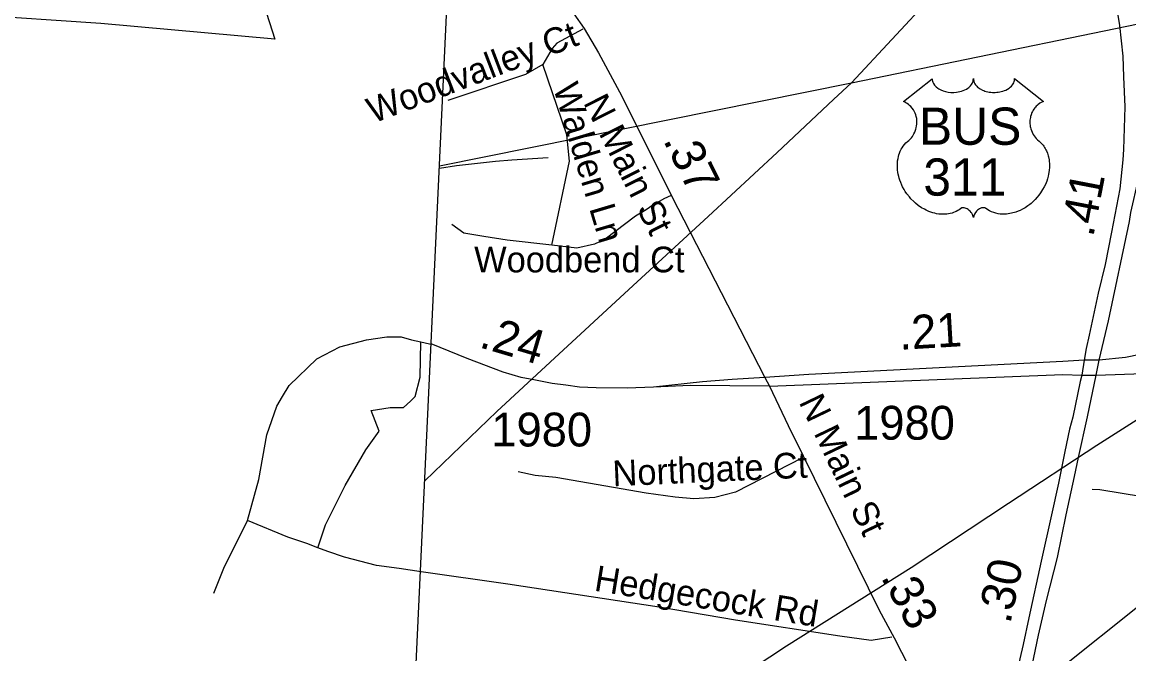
# Model space of a CAD drawing. Extents: x 1662474 to 1856135, y 779280 to 917889.
# Drawn here: x 1689866 to 1693953, y 821576 to 823910 of the extents above; entities that cross this region are included whole.
import ezdxf

# ---------------------------------------------------------------- set-up
doc = ezdxf.new("R2010")
doc.units = 0
for name, color, linetype in [('Exist Boundary Political City Limit New', 7, 'Continuous'), ('Exist Boundary Political CountyLine', 7, 'Continuous'), ('Exist Hydrographic Misc Water Feature', 7, 'Continuous'), ('Exist Road Non-System Type 51', 7, 'Continuous'), ('Exist Road Non-System Type 51 Label', 7, 'Continuous'), ('Exist Road Primary US Divided Attributed', 7, 'Continuous'), ('Exist Road Primary US Mileage Hundredths English Label', 7, 'Continuous'), ('Exist Road Primary US Shield CELL', 7, 'Continuous'), ('Exist Road Primary US Shield Number Label', 7, 'Continuous'), ('Exist Road Secondary Mileage Hundredths English Label', 7, 'Continuous'), ('Exist Road Secondary Mileage Tenths English Label', 7, 'Continuous'), ('Exist Road Secondary Type 51 Attributed', 7, 'Continuous'), ('Exist Road Secondary Type 51 Divided Attributed', 7, 'Continuous'), ('Exist Road Secondary Type 51 Label', 7, 'Continuous'), ('Exist Road Secondary Type 51 Number Label', 7, 'Continuous'), ('Exist Utilities Electrical Transmission Line', 7, 'Continuous'), ('Map Preparation Boundary City Limit Buffer Line', 7, 'Continuous')]:
    doc.layers.add(name, color=color, linetype=linetype)

msp = doc.modelspace()

# ---------------------------------------------------------------- linework, layer by layer
at = {"layer": 'Exist Boundary Political City Limit New'}
msp.add_lwpolyline([(1690797.9, 824417.9), (1690610.9, 824428.4), (1690696.4, 824166.9), (1690798.4, 823847.2), (1690156.9, 823905.5), (1689679, 823937.5)], dxfattribs=at)
at = {"layer": 'Exist Boundary Political CountyLine'}
msp.add_lwpolyline([(1690989.8, 814167.1), (1691300.1, 821093.4), (1691456.7, 824436.5)], dxfattribs=at)
at = {"layer": 'Exist Hydrographic Misc Water Feature'}
for points in [[(1691808.3, 823408.5), (1691674.3, 823400.5), (1691614.2, 823395.2), (1691470, 823379.2), (1691406.8, 823369.6)], [(1693817.8, 822185.1), (1693845.7, 822183.8), (1694004, 822157.5)]]:
    msp.add_lwpolyline(points, dxfattribs=at)
at = {"layer": 'Exist Road Non-System Type 51'}
for points in [[(1691936.1, 823884.5), (1691840.2, 823832), (1691823.2, 823812.4), (1691788.4, 823753.9)], [(1691788.4, 823753.9), (1691724.5, 823716.6), (1691437.6, 823620.8)], [(1691822.6, 823086.4), (1691887.2, 823396.4), (1691877.2, 823493.5), (1691788.4, 823753.9)], [(1692263.1, 823270.1), (1692235.6, 823256.8), (1692194.9, 823234.4), (1692169.9, 823216.9), (1692130.6, 823193.2), (1692019.2, 823107.9), (1691979.1, 823090.4), (1691914.9, 823074.9), (1691822.6, 823086.4)], [(1691822.6, 823086.4), (1691657.4, 823105), (1691570.8, 823118.7), (1691497, 823131), (1691452.1, 823163)], [(1690697.5, 822068.9), (1690739.8, 822220.5), (1690769.1, 822385.1), (1690806.1, 822490.9), (1690827.6, 822527.6), (1690851.4, 822568.2), (1690954.6, 822666.5), (1691038.9, 822710.1), (1691137.6, 822736.2), (1691213.1, 822747.9), (1691265.4, 822747.9), (1691303.2, 822736.2), (1691338.4, 822728.6), (1691370, 822721.7), (1691374.7, 822720.2)], [(1690957.9, 821967.8), (1690986.6, 822053.6), (1691059.2, 822198.9), (1691134.8, 822329.6), (1691184.1, 822399.2), (1691155.1, 822474.8), (1691224.8, 822486.4), (1691274.1, 822486.4), (1691300.4, 822509.7), (1691317.8, 822527.1), (1691335.5, 822598.9), (1691338.4, 822728.6)], [(1692748.4, 822300.6), (1692500.6, 822173.9), (1692423.8, 822153.9), (1692346.4, 822148.9), (1692277.2, 822155.2), (1692170.8, 822170.4), (1691836.9, 822228.2), (1691760.2, 822235.5), (1691697.5, 822249.4)], [(1690574.1, 821800.4), (1690610.6, 821893), (1690697.5, 822068.9)], [(1690957.9, 821967.8), (1690916.6, 821983.5), (1690846.4, 822007.2), (1690697.5, 822068.9)], [(1693077.8, 821638.1), (1693001.6, 821625.8), (1692885.1, 821641.8), (1692500.4, 821701.4), (1692218, 821749.4), (1691659.1, 821834.4), (1691339.5, 821879.4), (1691258.1, 821892.2), (1691174.9, 821902.7), (1691056.1, 821933.7), (1690994.1, 821954.1), (1690957.9, 821967.8)]]:
    msp.add_lwpolyline(points, dxfattribs=at)
at = {"layer": 'Exist Road Primary US Divided Attributed'}
for points in [[(1693621.4, 824772.1), (1693718.9, 824577.7), (1693802.8, 824370.4), (1693854.1, 824216.7), (1693900.7, 824014), (1693918.3, 823897.2), (1693931, 823784.9), (1693933.9, 823707.8), (1693938, 823596.8), (1693932.8, 823439.7), (1693931, 823401.6), (1693920, 823294.6), (1693889.1, 823133.9), (1693866.1, 823015.1), (1693839.5, 822908.4), (1693806.7, 822753.5), (1693795.6, 822704.4), (1693788.2, 822660.9)], [(1693843.8, 822661.8), (1693878.4, 822807.2), (1693955.8, 823173.4), (1693960.9, 823207.2), (1694016.6, 823453.3), (1694041.9, 823572.9), (1694057, 823643.7), (1694077.3, 823739.8), (1694092.9, 823824.1), (1694111, 823916.9)], [(1693788.2, 822660.9), (1693779.2, 822606.1)], [(1693832.9, 822605.4), (1693843.8, 822661.8)], [(1693779.2, 822606.1), (1693773.4, 822583.1), (1693745.8, 822450.7), (1693734.5, 822406.9), (1693716.9, 822324), (1693692.8, 822206.4), (1693667.9, 822089.6), (1693628.9, 821919.3), (1693584.2, 821709.2), (1693562.5, 821610.7), (1693534.9, 821489.2), (1693519.9, 821393.3), (1693506.8, 821298.7), (1693497.3, 821190.4), (1693497.8, 821134.8), (1693498.6, 821074.6)], [(1693550.9, 821059), (1693550.5, 821135.9), (1693552.9, 821231.5), (1693559.6, 821317.5), (1693570.9, 821397.1), (1693589.9, 821503.6), (1693619.1, 821645.6), (1693648.9, 821773.9), (1693689.2, 821932.5), (1693721.3, 822089.6), (1693752.5, 822231.2), (1693767.4, 822302.3), (1693799.9, 822451.8), (1693832.9, 822605.4)]]:
    msp.add_lwpolyline(points, dxfattribs=at)
at = {"layer": 'Exist Road Primary US Shield CELL'}
msp.add_lwpolyline([(1693227, 823701.1), (1693227.3, 823696.7), (1693228.4, 823691.5), (1693229.2, 823688.8), (1693231.7, 823683.6), (1693235.7, 823677.5), (1693241.3, 823671.6), (1693247.6, 823666.3), (1693251.9, 823663.6), (1693259.1, 823659.7), (1693267.4, 823656.2), (1693276.5, 823653.6), (1693285.9, 823651.7), (1693296.1, 823650.6), (1693306.2, 823650.4), (1693317.1, 823651.2), (1693329.2, 823653.5), (1693334.8, 823655), (1693341, 823657.1), (1693346.8, 823659.5), (1693353.1, 823662.9), (1693358.2, 823666.2), (1693362.2, 823669), (1693367.8, 823674.4), (1693372.3, 823680), (1693374.2, 823683.2), (1693375.8, 823686.2), (1693378.1, 823692.6), (1693378.7, 823695.4), (1693379.1, 823701.3), (1693379.5, 823696.4), (1693380, 823693.3), (1693380.8, 823690.3), (1693382.1, 823687.1), (1693384.3, 823682.5), (1693386.8, 823678.8), (1693391.6, 823673.2), (1693394.5, 823670.4), (1693397.2, 823668.2), (1693404.4, 823663.3), (1693412.9, 823659), (1693417, 823657.2), (1693421.3, 823655.7), (1693426.7, 823654), (1693432.3, 823652.7), (1693437.8, 823651.8), (1693443.5, 823651), (1693449.2, 823650.5), (1693453.9, 823650.4), (1693459.7, 823650.5), (1693465.1, 823650.8), (1693470.5, 823651.4), (1693476.5, 823652.4), (1693481.4, 823653.5), (1693487.8, 823655.2), (1693493.5, 823657.2), (1693498.6, 823659.4), (1693505.2, 823662.9), (1693510.6, 823666.2), (1693514.5, 823669.4), (1693519.1, 823673.6), (1693523.5, 823678.7), (1693526.1, 823682.4), (1693527.9, 823686.3), (1693529.6, 823690.3), (1693530.6, 823694.5), (1693531.1, 823698.2), (1693531.2, 823701.4), (1693637.5, 823616.7), (1693635, 823615.8), (1693629.2, 823613), (1693624.6, 823610.3), (1693617.3, 823605.1), (1693614.2, 823602.3), (1693611, 823599.3), (1693608.2, 823596.2), (1693605.6, 823593.2), (1693602.5, 823589), (1693599.8, 823584.7), (1693597.1, 823580), (1693595.1, 823575.9), (1693591.8, 823567.4), (1693590.3, 823562), (1693589.3, 823557.4), (1693588, 823547.9), (1693587.7, 823543.4), (1693587.7, 823538.9), (1693587.9, 823534.2), (1693588.4, 823529.7), (1693589.2, 823525), (1693590, 823520.8), (1693591.3, 823515.8), (1693593.2, 823509.8), (1693595.5, 823504.1), (1693600.3, 823494.9), (1693606.6, 823485.5), (1693611, 823480.2), (1693615.4, 823475.7), (1693622, 823470.2), (1693625.5, 823467), (1693629.6, 823462.9), (1693636.3, 823455.2), (1693639, 823451.6), (1693641.7, 823447.5), (1693644.2, 823443.3), (1693646.7, 823438.8), (1693648.7, 823434.8), (1693652.5, 823425.7), (1693655.2, 823416.8), (1693656.5, 823412.2), (1693658.4, 823401.8), (1693659.2, 823396.6), (1693660, 823386.4), (1693660, 823374.1), (1693659.1, 823362.5), (1693656.9, 823348.8), (1693655.1, 823340.7), (1693652.3, 823331.2), (1693649.6, 823323), (1693644.7, 823310.8), (1693640.4, 823302), (1693634.8, 823291.7), (1693631, 823285.5), (1693626.5, 823278.9), (1693621, 823271.2), (1693614.4, 823263), (1693606.6, 823254.4), (1693600.2, 823248.1), (1693592, 823240.7), (1693586.9, 823236.5), (1693579.8, 823231.1), (1693570, 823224.6), (1693560.3, 823219), (1693552.1, 823214.8), (1693544.8, 823211.7), (1693535.4, 823208.1), (1693519.7, 823203.8), (1693514, 823202.6), (1693507.2, 823201.6), (1693500.9, 823200.9), (1693494.7, 823200.6), (1693486.5, 823200.6), (1693478.2, 823201.2), (1693470.4, 823202.3), (1693462.4, 823204), (1693453.9, 823206.5), (1693446.2, 823209.5), (1693438.4, 823213.4), (1693425.3, 823221.7), (1693421.5, 823223.7), (1693419.3, 823224.2), (1693414.2, 823224.5), (1693409.5, 823223.5), (1693404.6, 823221.5), (1693401.6, 823220), (1693397.7, 823217.4), (1693394.7, 823215), (1693391, 823211.6), (1693388.5, 823208.7), (1693386.6, 823206.4), (1693382.9, 823200.6), (1693381.6, 823197.8), (1693380.2, 823194.2), (1693379, 823189), (1693377.3, 823195.6), (1693375.4, 823200), (1693373.1, 823203.8), (1693370.8, 823207.1), (1693367.1, 823211.4), (1693363.7, 823214.6), (1693359.7, 823217.8), (1693355.5, 823220.4), (1693352, 823222.2), (1693348.9, 823223.4), (1693345.1, 823224.3), (1693341.9, 823224.6), (1693339.4, 823224.5), (1693335.8, 823223.7), (1693331, 823220.2), (1693326.5, 823217.1), (1693321.5, 823214), (1693315.6, 823210.9), (1693311.3, 823208.9), (1693306.1, 823206.8), (1693300.1, 823204.8), (1693293.6, 823203.1), (1693286.9, 823201.8), (1693281, 823200.9), (1693274.6, 823200.3), (1693268.9, 823200.1), (1693262.9, 823200.2), (1693257.4, 823200.6), (1693250.9, 823201.2), (1693242.9, 823202.4), (1693236.2, 823203.9), (1693229.2, 823205.8), (1693222, 823208), (1693214.2, 823211), (1693204.6, 823215.2), (1693197.9, 823218.6), (1693187.2, 823224.7), (1693174.8, 823233.3), (1693165.4, 823240.9), (1693158.6, 823247.2), (1693148.5, 823257.5), (1693142.5, 823264.2), (1693133.2, 823276.2), (1693127.2, 823285), (1693123.4, 823291.4), (1693117.7, 823301.7), (1693114.6, 823308.1), (1693110.6, 823317.6), (1693107.4, 823326.2), (1693104.8, 823334.3), (1693103.4, 823339.5), (1693101.4, 823348.6), (1693100.2, 823355.1), (1693099, 823364), (1693098.3, 823373.3), (1693098.2, 823381.9), (1693098.4, 823389.1), (1693099.2, 823397.4), (1693100.6, 823406.3), (1693102.3, 823413.9), (1693103.9, 823419.4), (1693106.1, 823426), (1693109.1, 823433.4), (1693112.6, 823440.4), (1693116, 823446.2), (1693120.2, 823452.5), (1693124.3, 823457.8), (1693129.8, 823463.8), (1693135.4, 823469.2), (1693140.6, 823473.4), (1693146.7, 823479.4), (1693149.9, 823483), (1693153.8, 823488.1), (1693156.9, 823492.8), (1693159.3, 823497), (1693162.6, 823503.3), (1693164.5, 823507.9), (1693166.9, 823515.1), (1693168.2, 823520.1), (1693169.4, 823526.6), (1693170.2, 823532.6), (1693170.6, 823540.2), (1693170.4, 823546.5), (1693169.6, 823553.9), (1693168.2, 823560.9), (1693166.5, 823567.1), (1693163.9, 823574.1), (1693161.5, 823579.2), (1693157.4, 823586.2), (1693152.9, 823592.7), (1693148.2, 823598), (1693143.5, 823602.7), (1693139, 823606.2), (1693134.7, 823609.3), (1693129.3, 823612.5), (1693124, 823615.1), (1693120.8, 823616.4)], close=True, dxfattribs=at)
at = {"layer": 'Exist Road Secondary Type 51 Attributed'}
for points in [[(1691619.7, 824282.9), (1691726.9, 824155.7), (1691867.5, 823987.1), (1691889.4, 823959), (1691903.1, 823941.3), (1691940.8, 823886.4), (1691993.8, 823796.2), (1692081.1, 823636.4), (1692264.2, 823268.4), (1692608.1, 822597.9)], [(1692197.3, 822561.5), (1692100.7, 822557.3), (1691985.8, 822558.9), (1691924.5, 822562.1), (1691874.2, 822568.4), (1691823.3, 822574.7), (1691754.9, 822588.1), (1691708.5, 822597.9), (1691642.6, 822617.4), (1691509.6, 822667.4), (1691376.4, 822721.2)], [(1692608.1, 822597.9), (1692625.8, 822565.4)], [(1692625.8, 822565.4), (1692332.8, 822567.4), (1692197.3, 822561.5)], [(1692625.8, 822565.4), (1692694.4, 822420.2), (1692750.3, 822307.7), (1693031.1, 821737.2), (1693086.6, 821635.2), (1693249, 821317.4), (1693299.6, 821211.2), (1693339.3, 821154.6), (1693368.3, 821133.4), (1693398.7, 821117.1), (1693498.6, 821074.6)]]:
    msp.add_lwpolyline(points, dxfattribs=at)
at = {"layer": 'Exist Road Secondary Type 51 Divided Attributed'}
for points in [[(1694921.8, 823148.3), (1694874.6, 823126.6), (1694778.7, 823078.2), (1694520.4, 822930.6), (1694354.1, 822830.1), (1694244.9, 822767.9), (1694165.2, 822732.9), (1694071.7, 822702.5), (1694028.3, 822690.8), (1693994.7, 822682), (1693941.1, 822671.1), (1693843.8, 822661.8)], [(1693832.9, 822605.4), (1694042.1, 822612.7), (1694193.2, 822612.7), (1694470.2, 822629.4), (1694730.6, 822656.4), (1694984.6, 822685.4), (1695105.8, 822699.7), (1695440.1, 822744.7), (1695733.4, 822794.7), (1695803.2, 822807.4), (1695910.9, 822828.5), (1696165.1, 822883.8), (1696461.6, 822952.4), (1696643.2, 822998.2), (1696733.1, 823031.7)], [(1693788.2, 822660.9), (1693709.5, 822656.3), (1692771.8, 822608.1), (1692608.1, 822597.9)], [(1693843.8, 822661.8), (1693814.2, 822661.8), (1693788.2, 822660.9)], [(1692608.1, 822597.9), (1692487.7, 822590.1), (1692378.4, 822581.6), (1692197.3, 822561.5)], [(1692625.8, 822565.4), (1693709.5, 822609), (1693779.2, 822606.1)], [(1693779.2, 822606.1), (1693832.9, 822605.4)]]:
    msp.add_lwpolyline(points, dxfattribs=at)
at = {"layer": 'Exist Utilities Electrical Transmission Line'}
msp.add_line((1691407.2, 823379.4), (1692929.2, 823686.1), dxfattribs=at)
for points in [[(1692929.2, 823686.1), (1695261.2, 824166.9), (1701520.4, 828105.5)], [(1691247.7, 819923.8), (1691765.1, 820266.6), (1692074.2, 820473), (1692211.2, 820558.9), (1693016.8, 821102.4), (1693308.1, 821209.1), (1694387.8, 822071.7), (1696193.9, 823484.3), (1697905.9, 824894), (1698412.5, 825294.6)], [(1691281.1, 820669.4), (1691930.6, 821110.2), (1692261, 821324.6), (1692688.2, 821606.1), (1693149.5, 821895.1), (1693508.3, 822133.3), (1693834.7, 822347.8), (1694257.8, 822617.2), (1694572.2, 822826), (1695106.1, 823170.1), (1695704.6, 823551.8), (1696125.7, 823829.2), (1696512.5, 824075.1), (1696907.6, 824334.9), (1697211.8, 824533.6), (1697578.5, 824773.6), (1697878.7, 824962.5), (1698227.3, 825188.7), (1698412.5, 825294.6)], [(1692929.2, 823686.1), (1693226.7, 824007), (1693425.5, 824246.9), (1693627.9, 824470.7), (1693863.1, 824750.3), (1694114.5, 825045.6)], [(1691352.7, 822215.4), (1691619.4, 822472.2), (1691815.4, 822654.1), (1692106.4, 822922.9), (1692399.5, 823191.7), (1692654.2, 823429.1), (1692862.5, 823624.8), (1692929.2, 823686.1)]]:
    msp.add_lwpolyline(points, dxfattribs=at)
at = {"layer": 'Map Preparation Boundary City Limit Buffer Line'}
msp.add_lwpolyline([(1690797.9, 824417.9), (1690610.9, 824428.4), (1690696.4, 824166.9), (1690798.4, 823847.2), (1690156.9, 823905.5), (1689679, 823937.5)], dxfattribs=at)

# ---------------------------------------------------------------- texts
at = {"layer": 'Exist Road Non-System Type 51 Label'}
for s, rotation, p in [('Woodvalley Ct', 20.9091, (1691162.2, 823534.9)), ('Walden Ln', 286.6368, (1691825.9, 823669.1)), ('Northgate Ct', 2.5828, (1692048.1, 822195.1)), ('Hedgecock Rd', 350.7174, (1691975.2, 821810.1))]:
    msp.add_text(s, height=95, rotation=rotation, dxfattribs=at).set_placement(p)
msp.add_text('Woodbend Ct', height=95, dxfattribs=at).set_placement((1691535.1, 822985.7))
at = {"layer": 'Exist Road Primary US Mileage Hundredths English Label'}
for s, rotation, p in [('.41', 79.108, (1693821.4, 823113)), ('.30', 77.9924, (1693515, 821684.2))]:
    msp.add_text(s, height=125, rotation=rotation, dxfattribs=at).set_placement(p)
at = {"layer": 'Exist Road Primary US Shield Number Label'}
for s, p in [('BUS', (1693178, 823457)), ('311', (1693194.1, 823269.1))]:
    msp.add_text(s, height=137.5, dxfattribs=at).set_placement(p)
at = {"layer": 'Exist Road Secondary Mileage Hundredths English Label'}
for s, rotation, p in [('.37', 296.4511, (1692231.7, 823474)), ('.24', 343.5049, (1691549.7, 822710.1)), ('.33', 298.5414, (1693035.6, 821859.8))]:
    msp.add_text(s, height=125, rotation=rotation, dxfattribs=at).set_placement(p)
at = {"layer": 'Exist Road Secondary Mileage Tenths English Label'}
msp.add_text('.21', height=125, rotation=3.383, dxfattribs=at).set_placement((1693107, 822699.3))
at = {"layer": 'Exist Road Secondary Type 51 Label'}
for rotation, p in [(296.7344, (1691937, 823613.3)), (295.6574, (1692732.9, 822507))]:
    msp.add_text('N Main St', height=95, rotation=rotation, dxfattribs=at).set_placement(p)
at = {"layer": 'Exist Road Secondary Type 51 Number Label'}
for p in [(1691598.7, 822342.5), (1692938.5, 822367.6)]:
    msp.add_text('1980', height=125, dxfattribs=at).set_placement(p)

doc.saveas('drawing.dxf')
